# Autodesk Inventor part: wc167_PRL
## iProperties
Shininess: 64.0
Length Units: 11272
Angle Units: 11279
Time Units: 11290
Mass Units: 11286
Length Display Precision: 3
Angle Display Precision: 2
Compacted: True
Part Number: wc167_PRL
Document SubType Name: Modeling
Created: 2004-08
Designer: John Blackburn
Manufacturer: Standard
Standards Organization: Custom
Material: Phenolic
Density: 0.0
Volumn: 0.0
Area: 0.0
PropertySet Name: Model Information
Control State: 0
Master: False
Checked Out: False
Author: John Blackburn
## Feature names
1. Revolution1
